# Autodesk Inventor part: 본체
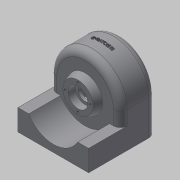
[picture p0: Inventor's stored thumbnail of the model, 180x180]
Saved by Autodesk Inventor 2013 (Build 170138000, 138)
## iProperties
Created: 2015-02
Part Number: 본체
Material: 일반
Document SubType Name: Modeling
Designer: Administrator
Density: 1 g/cm^3
Author: Administrator
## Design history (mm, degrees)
sketch "스케치1"
  geometry: L1 (-50, 0)-(-50, -50); L2 (50, 0)-(50, -50); L3 (50, -50)-(-50, -50); A1 r 50 centre (0, 0) between (50, 0) and (-50, 0); 1 further point
  constraints: 6 end point, 2 point on circle, 2 tangent, 1 centre point, 1 coincident, 1 parallel, 1 perpendicular, 1 vertical
  dimensions: "d0" = 100 diameter of A1; "d1" = 50 distance from line of L3 A1.centre
extrude "돌출1" new body sketch "스케치1" stored distance "d2" = 50; taper "d3" = 0 deg
sketch "스케치3"
  geometry: L1 (50, 50)-(-50, 50); L2 (-50, 50)-(-50, 20); L3 (-50, 20)-(50, 20); L4 (50, 20)-(50, 50)
  constraints: 8 end point, 2 parallel, 1 horizontal, 1 perpendicular
  dimensions: "d4" = 100 distance of L3.end L2.end; "d5" = 30 distance of L2.end L1.end
extrude "돌출2" join sketch "스케치3" distance "d6" = 95; taper "d7" = 0 deg
sketch "스케치5"
  geometry: L1 (-40, 0)-(40, 0); L2 (25, -50)-(-70, -50) reference; L3 (-35, 0)-(-35, 21.36); L4 (-25, 50)-(-25, 0) reference; L5 (-35, 21.36)-(-25, 25); L6 (-25, 25)-(-25, 0); L7 (-35, 0)-(-25, 0); 1 further point
  constraints: 10 end point, 1 collinear, 1 horizontal, 1 midpoint, 1 perpendicular, 1 point on line
  dimensions: "d8" = 50 distance between parallel lines of L1 L2; "d9" = 10 distance between parallel lines of L4 L3; "d10" = 50 diameter of L5.end L1; "d11" = 110 deg angle of L4 L5
sketch "스케치6"
  geometry: L1 (50, -20)-(-50, -20) reference; L2 (-34.641, -20)-(34.641, -20); A1 r 40 centre (0, 0) between (-34.641, -20) and (34.641, -20); 1 further point
  constraints: 2 end point, 2 point on circle, 2 point on line, 1 centre point, 1 coincident, 1 collinear
  dimensions: "d12" = 80 diameter of A1
extrude "돌출3" cut sketch "스케치6" stored distance "d13" = 35; taper "d14" = 0 deg
revolve "회전1" stored, may be unused: angle "d15" = 90 deg
hole "구멍1" diameter "d18" = 20; stored, may be unused: countersink angle "d22" = 90 deg, drill point angle "d24" = 0 deg; dims "d16" = 10, "d17" = 10, "d19" = 6, "d20" = 28, "d21" = 10, "d23" = 4
sketch "스케치7"
  geometry: L1 (25, 0)-(25, 50) reference; L2 (25, -50)-(25, 0) reference; L3 (-29.31, 0)-(29.31, 0); L4 (25, 20)-(34, 20); L5 (34, 20)-(34, 0); L6 (25, 20)-(25, 0); L7 (34, 0)-(25, 0); 2 further points
  constraints: 10 end point, 2 collinear, 2 perpendicular, 1 coincident, 1 midpoint, 1 parallel, 1 point on line
  dimensions: "d27" = 40 diameter of L4 L3; "d29" = 9 distance of L4.start L4.end
revolve "회전2" sketch "스케치7" stored, may be unused: angle "d30" = 90 deg
fillet "모깎기1" dims "d31" = 10
fillet "모깎기2" dims "d32" = 10
fillet "모깎기3" dims "d33" = 3
fillet "모깎기4" dims "d34" = 3
sketch "스케치11"
  geometry: L1 (-50, -20)-(-50, 0) reference; L2 (-50, -50)-(-50, -20) reference; L3 (50, -20)-(50, -50) reference; L4 (50, 0)-(50, -20) reference; L5 (50, 0)-(50, -50) reference; L6 (50, -50)-(-50, -50) reference; L7 (-50, -50)-(-50, 0) reference; L8 (-46, -50)-(-46, -20); L9 (-46, -20)-(-46, 0); L10 (46, 0)-(46, -20); L11 (46, -20)-(46, -50); L12 (-46, -50)-(46, -50); A1 r 50 centre (0, 0) between (50, 0) and (-50, 0) reference; A2 r 50 centre (0, 0) between (50, 0) and (-50, 0) reference; A3 r 46 centre (0, 0) between (46, 0) and (-46, 0); 1 further point
  constraints: 10 end point, 4 parallel, 2 point on circle, 1 centre point, 1 collinear
  dimensions: "d53" = 4 distance between parallel lines of L9 L1; "d54" = 4 radial gap between concentric circles of A3 A1; "d55" = 4 distance between parallel lines of L3 L11
extrude "돌출5" cut sketch "스케치11" stored distance "d56" = 42; taper "d57" = 0 deg
sketch "스케치12" dims "d58" = 36
  geometry: C1 r 14 at (0, 0) reference; C2 r 21.36 at (0, 0) reference; 2 further points
  constraints: 2 vertical alignment, 1 coincident, 2 other
hole "구멍2" sketch "스케치12" at (0, 18) diameter "d59" = 3.459; stored, may be unused: countersink angle "d63" = 90 deg, drill point angle "d65" = 118 deg; dims "d60" = 6, "d61" = 4, "d62" = 2, "d64" = 9
sketch "스케치13"
  geometry: L1 (0, 85)-(0, 0) reference; L2 (100, 0)-(0, 0) reference; 5 further points
  constraints: 2 horizontal alignment, 2 vertical alignment
  dimensions: "d69" = 33 distance of point (8.25, 42) point (8.25, 9); "d71" = 9 distance from line of point (8.25, 9) L2; "d72" = 83.5 distance of point (8.25, 9) point (91.75, 9); "d73" = 8.25 distance from line of L1 point (8.25, 9)
hole "구멍3" sketch "스케치13" at (8.25, 9), (8.25, 42), (91.75, 42), (91.75, 9) diameter "d74" = 5.134; stored, may be unused: countersink angle "d78" = 90 deg, drill point angle "d80" = 118 deg; dims "d75" = 10, "d76" = 4, "d77" = 2, "d79" = 13
node "작업 평면1"
sketch "스케치14"
  geometry: L1 (-40, 25)-(40, 25) reference; 2 further points
  constraints: 1 coincident, 1 other
feature "엠보싱1" sketch "스케치14" dims "d0" = 100, "d1" = 50, "d10" = 50, "d81" = 1, "d82" = 0
hole "구멍4" diameter "d85" = 20; stored, may be unused: countersink angle "d89" = 90 deg, drill point angle "d91" = 0 deg; dims "d83" = 10, "d84" = 10, "d86" = 10, "d87" = 28, "d88" = 8, "d90" = 2
node "솔리드1"
pattern_circular "원형 패턴1" dims angle "d67" = 360 deg
node "절단 모서리 투영1"
